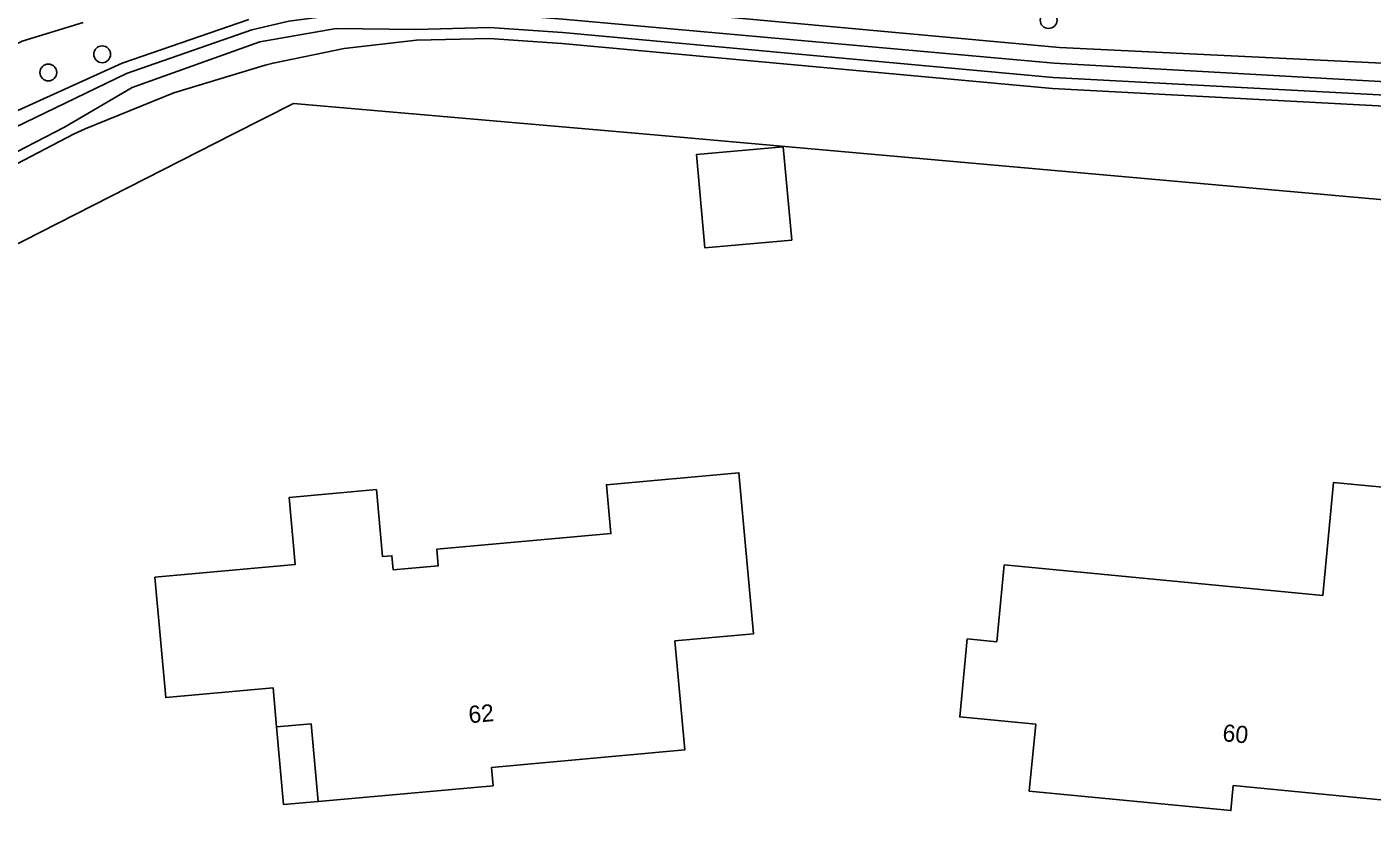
# Model space of a CAD drawing. Extents: x 162722 to 165104, y 384719 to 386284.
# Drawn here: x 163774.4 to 163852.8, y 385210.4 to 385256.2 of the extents above; entities that cross this region are included whole.
import ezdxf

# ---------------------------------------------------------------- set-up
doc = ezdxf.new("R2010")
doc.units = 0
for name, color, linetype in [('IMGEO_Boom', 7, 'Continuous'), ('IMGEO_Erf', 7, 'Continuous'), ('IMGEO_Gemengd_bos', 7, 'Continuous'), ('IMGEO_Groenvoorziening', 7, 'Continuous'), ('IMGEO_Oever', 7, 'Continuous'), ('IMGEO_Pand', 7, 'Continuous'), ('IMGEO_Pand_nummerreeks', 7, 'Continuous'), ('IMGEO_Pand_overbouw', 7, 'Continuous'), ('IMGEO_Rijbaan_lokaal_halfverhard', 7, 'Continuous'), ('IMGEO_Waterloop', 7, 'Continuous')]:
    doc.layers.add(name, color=color, linetype=linetype)

msp = doc.modelspace()

# ---------------------------------------------------------------- linework, layer by layer
at = {"layer": 'IMGEO_Boom'}
for centre in [(163833.925, 385256.638), (163778.819, 385254.644), (163775.68, 385253.584)]:
    msp.add_circle(centre, 0.489, dxfattribs=at)
at = {"layer": 'IMGEO_Erf'}
msp.add_lwpolyline([(163910.133, 385241.022), (163886.57, 385243.212), (163810.294, 385250), (163789.963, 385251.774), (163786.457, 385250), (163728.314, 385220.373), (163748.353, 385181.193), (163771.607, 385192.983), (163778.051, 385196.25), (163781.022, 385197.731)], dxfattribs=at)
for points in [[(163813.909, 385243.356), (163813.415, 385248.799), (163818.474, 385249.259), (163818.969, 385243.816)], [(163801.59, 385212.021), (163791.394, 385211.098), (163790.983, 385215.629), (163788.971, 385215.446), (163788.764, 385217.726), (163782.519, 385217.16), (163781.884, 385224.171), (163790.05, 385224.91), (163789.696, 385228.814), (163794.785, 385229.274), (163795.138, 385225.369), (163795.685, 385225.418), (163795.758, 385224.601), (163798.387, 385224.839), (163798.3, 385225.795), (163808.438, 385226.712), (163808.18, 385229.56), (163815.888, 385230.257), (163816.737, 385220.875), (163812.165, 385220.461), (163812.74, 385214.106), (163801.494, 385213.088)], [(163832.802, 385211.701), (163833.177, 385215.598), (163828.751, 385216.024), (163829.189, 385220.571), (163830.909, 385220.405), (163831.34, 385224.888), (163849.885, 385223.104), (163850.519, 385229.698), (163855.024, 385229.265), (163854.332, 385222.072), (163857.298, 385221.787), (163856.73, 385215.887), (163856.251, 385210.91), (163844.678, 385212.023), (163844.539, 385210.572)]]:
    msp.add_lwpolyline(points, close=True, dxfattribs=at)
at = {"layer": 'IMGEO_Gemengd_bos'}
msp.add_lwpolyline([(163728.314, 385220.373), (163786.457, 385250), (163789.963, 385251.774), (163810.294, 385250), (163886.57, 385243.212), (163910.133, 385241.022), (163910.573, 385246.191), (163871.205, 385250), (163855.681, 385251.502), (163834.151, 385252.659), (163805.574, 385255.278), (163801.35, 385255.558), (163797.117, 385255.46), (163792.91, 385254.985), (163788.763, 385254.135), (163788.312, 385254.019), (163782.99, 385252.393), (163777.835, 385250.299), (163777.194, 385250), (163772.987, 385247.809), (163761.54, 385242.598), (163726.113, 385224.584)], close=True, dxfattribs=at)
at = {"layer": 'IMGEO_Groenvoorziening'}
for points in [[(163805.914, 385257.654), (163834.561, 385255.032), (163855.757, 385254.001)], [(163777.7, 385256.496), (163774.167, 385255.4), (163762.995, 385250), (163759.521, 385248.321), (163759.373, 385248.264), (163755.332, 385246.722), (163719.457, 385228.444), (163714.908, 385226.251), (163709.029, 385223.291), (163695.982, 385216.891), (163624.905, 385180.679)], [(163772.877, 385250.908), (163779.988, 385254.117), (163787.358, 385256.677)]]:
    msp.add_lwpolyline(points, dxfattribs=at)
at = {"layer": 'IMGEO_Oever'}
for points in [[(163723.635, 385225.559), (163733.915, 385230.675), (163760.585, 385244.169), (163771.339, 385249.229), (163780.225, 385253.523), (163787.537, 385256.063), (163789.688, 385256.57), (163792.368, 385256.924), (163797.592, 385257.005), (163801.506, 385257.021), (163805.639, 385256.698), (163834.243, 385254.136), (163855.663, 385252.919), (163892.589, 385249.365), (163910.526, 385247.41)], [(163855.757, 385254.001), (163834.561, 385255.032), (163805.914, 385257.654)], [(163910.571, 385246.849), (163910.38, 385246.851), (163871.267, 385250.636), (163855.729, 385252.139), (163834.197, 385253.296), (163805.624, 385255.915), (163801.364, 385256.197), (163797.074, 385256.098), (163792.447, 385256.152), (163787.987, 385255.362), (163780.569, 385252.718), (163776.621, 385250.4), (163772.707, 385248.383), (163761.263, 385243.174), (163734.828, 385229.732), (163726.485, 385225.462), (163724.159, 385224.28)], [(163787.358, 385256.677), (163779.988, 385254.117), (163772.877, 385250.908)], [(163772.987, 385247.809), (163777.194, 385250), (163777.835, 385250.299), (163782.99, 385252.393), (163788.312, 385254.019), (163788.763, 385254.135), (163792.91, 385254.985), (163797.117, 385255.46), (163801.35, 385255.558), (163805.574, 385255.278), (163834.151, 385252.659), (163855.681, 385251.502)]]:
    msp.add_lwpolyline(points, dxfattribs=at)
at = {"layer": 'IMGEO_Pand'}
for points in [[(163818.969, 385243.816), (163818.474, 385249.259), (163813.415, 385248.799), (163813.909, 385243.356)], [(163801.59, 385212.021), (163801.494, 385213.088), (163812.74, 385214.106), (163812.165, 385220.461), (163816.737, 385220.875), (163815.888, 385230.257), (163808.18, 385229.56), (163808.438, 385226.712), (163798.3, 385225.795), (163798.387, 385224.839), (163795.758, 385224.601), (163795.685, 385225.418), (163795.138, 385225.369), (163794.785, 385229.274), (163789.696, 385228.814), (163790.05, 385224.91), (163781.884, 385224.171), (163782.519, 385217.16), (163788.764, 385217.726), (163788.971, 385215.446), (163790.983, 385215.629), (163791.394, 385211.098)], [(163830.909, 385220.405), (163829.189, 385220.571), (163828.751, 385216.024), (163833.177, 385215.598), (163832.802, 385211.701), (163844.539, 385210.572), (163844.678, 385212.023), (163856.251, 385210.91), (163856.73, 385215.887), (163857.298, 385221.787), (163854.332, 385222.072), (163855.024, 385229.265), (163850.519, 385229.698), (163849.885, 385223.104), (163831.34, 385224.888)]]:
    msp.add_lwpolyline(points, close=True, dxfattribs=at)
at = {"layer": 'IMGEO_Pand_overbouw'}
msp.add_lwpolyline([(163790.983, 385215.629), (163788.971, 385215.446), (163789.382, 385210.916), (163791.394, 385211.098)], close=True, dxfattribs=at)
at = {"layer": 'IMGEO_Rijbaan_lokaal_halfverhard'}
msp.add_lwpolyline([(163768.949, 385256.914), (163756.6, 385251.831), (163756.237, 385251.657), (163755.859, 385251.516), (163752.626, 385250), (163745.512, 385246.664), (163735.822, 385241.702), (163725.535, 385236.149), (163717.752, 385231.973), (163719.457, 385228.444), (163755.332, 385246.722), (163759.373, 385248.264), (163759.521, 385248.321), (163762.995, 385250), (163774.167, 385255.4), (163777.7, 385256.496)], dxfattribs=at)
at = {"layer": 'IMGEO_Waterloop'}
for points in [[(163910.526, 385247.41), (163892.589, 385249.365), (163855.663, 385252.919), (163834.243, 385254.136), (163805.639, 385256.698), (163801.506, 385257.021), (163797.592, 385257.005), (163792.368, 385256.924), (163789.688, 385256.57), (163787.537, 385256.063), (163780.225, 385253.523), (163771.339, 385249.229), (163760.585, 385244.169), (163733.915, 385230.675), (163723.635, 385225.559)], [(163724.159, 385224.28), (163726.485, 385225.462), (163734.828, 385229.732), (163761.263, 385243.174), (163772.707, 385248.383), (163776.621, 385250.4), (163780.569, 385252.718), (163787.987, 385255.362), (163792.447, 385256.152), (163797.074, 385256.098), (163801.364, 385256.197), (163805.624, 385255.915), (163834.197, 385253.296), (163855.729, 385252.139), (163871.267, 385250.636), (163910.38, 385246.851)]]:
    msp.add_lwpolyline(points, dxfattribs=at)

# ---------------------------------------------------------------- texts
at = {"layer": 'IMGEO_Pand_nummerreeks'}
for s, rotation, p in [('62', 5.17529, (163800.189, 385215.656)), ('60', 354.50664, (163844.018, 385214.619))]:
    msp.add_text(s, height=1, rotation=rotation, dxfattribs=at).set_placement(p)

doc.saveas('drawing.dxf')
